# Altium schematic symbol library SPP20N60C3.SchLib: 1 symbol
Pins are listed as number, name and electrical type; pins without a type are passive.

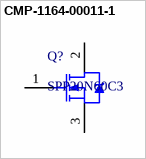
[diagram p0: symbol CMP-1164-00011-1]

## CMP-1164-00011-1
designator Q?, comment SPP20N60C3
N-Channel CoolMOS Power-Transistor, 600 V VDS, 20.7 A ID, -55 to 150 degC, PG-TO220-3-1, Tube, Green; Manufacturer: Infineon; RDS (on) (max): 190Â mOhm; VDS (max): 600Â V; IDpuls (max): 62.1Â A; RthJA (max): 62Â K/W; Ptot (max): 208Â W; Polarity: N; VGS(th) (max): 3.9Â V; ID (max): 20.7Â A; Green: TRUE; VGS(th) (min): 2.1Â V; QG: 87Â nC; RthJC (max): 0.6Â K/W
footprint INF-PG-TO220-3-1 (FM, 3-Leads, Body 10x4.4mm, Pitch 2.54mm)
pins: 1 GATE, 2 DRAIN, 3 SOURCE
